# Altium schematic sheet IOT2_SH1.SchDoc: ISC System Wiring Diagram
size B; DrawnBy: Filiberto Clara; Engineer: Filiberto Clara; Organization: LIGO Laboratory; Address1: California Institute of Technology; Address2: Massachusetts Institute of Technology; SheetNumber: 24; SheetTotal: 37
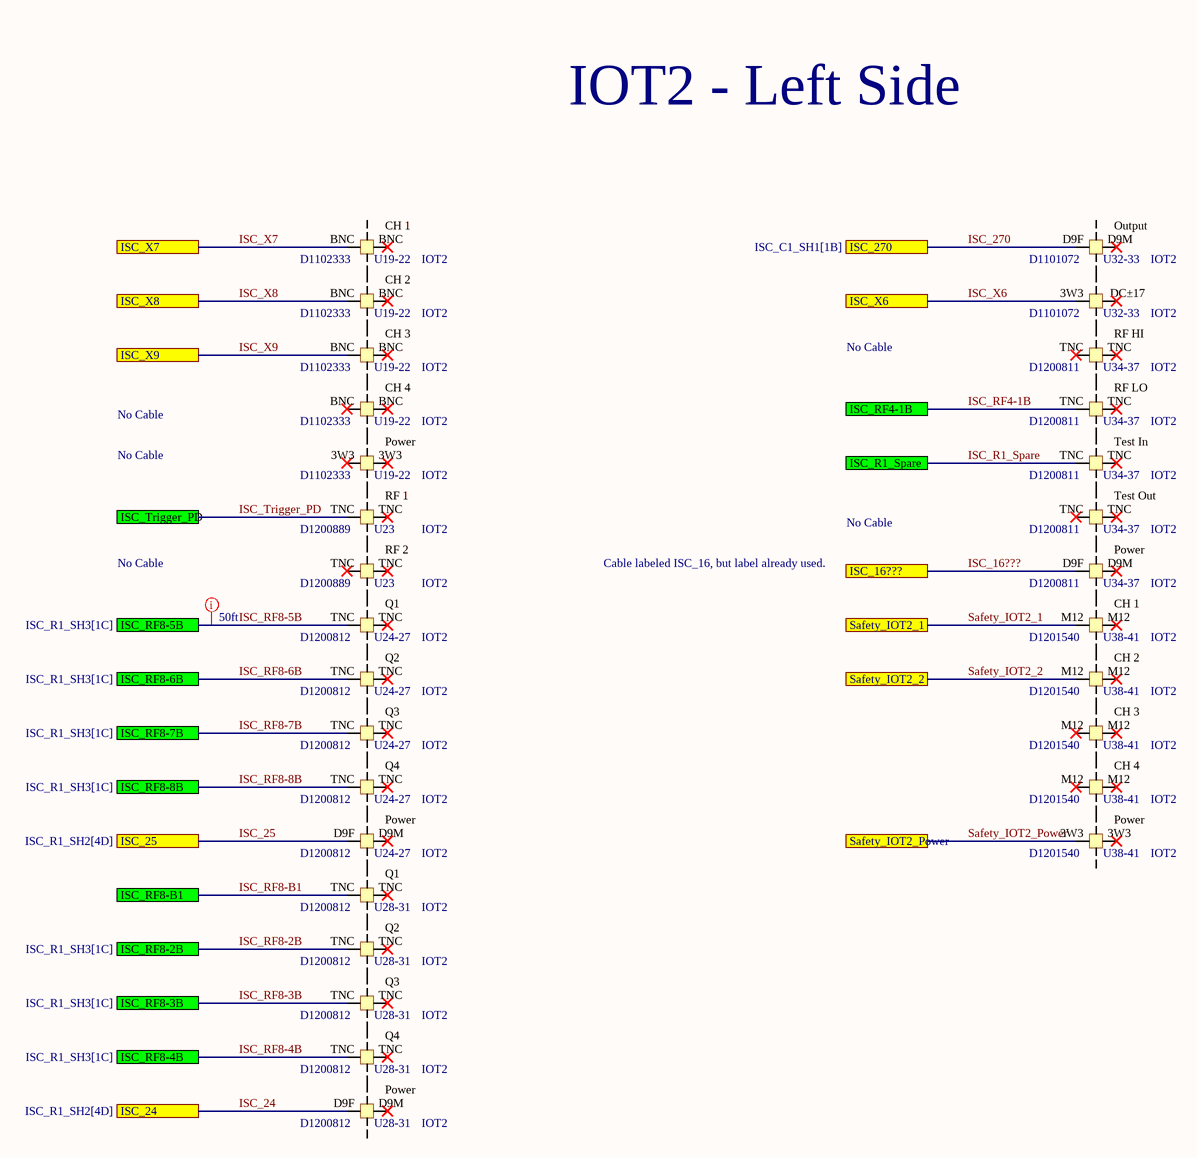
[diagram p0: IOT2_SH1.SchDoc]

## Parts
C_IOT2_1  DCC: D1102333  Rack: IOT2  Slot: U19-22  (hidden comment: Patch Panel Analog Video)  (parts A,B,C,D,E of 5)
C_IOT2_2  DCC: D1200889  Rack: IOT2  Slot: U23  (hidden comment: Patch Panel Broadband PD)  (parts A,B of 2)
C_IOT2_3  DCC: D1200812  Rack: IOT2  Slot: U24-27  (hidden comment: Patch Panel Single Frequency WFS RFPD)  (parts A,B,C,D,E of 5)
C_IOT2_4  DCC: D1200812  Rack: IOT2  Slot: U28-31  (hidden comment: Patch Panel Single Frequency WFS RFPD)  (parts A,B,C,D,E of 5)
C_IOT2_5  DCC: D1101072  Rack: IOT2  Slot: U32-33  (hidden comment: Patch Panel DCPD Interface)  (parts A,B of 2)
C_IOT2_6  DCC: D1200811  Rack: IOT2  Slot: U34-37  (hidden comment: Patch Panel Dual Frequency LSC RFPD)  (parts A,B,C,D,E of 5)
C_IOT2_7  DCC: D1201540  Rack: IOT2  Slot: U38-41  (hidden comment: Patch Panel Interlocks/Lighting)  (parts A,B,C,D,E of 5)

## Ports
ISC_16???, ISC_24 (see ISC_R1_SH2[4D]), ISC_25 (see ISC_R1_SH2[4D]), ISC_270 (see ISC_C1_SH1[1B]), ISC_R1_Spare, ISC_RF4-1B, ISC_RF8-2B (see ISC_R1_SH3[1C]), ISC_RF8-3B (see ISC_R1_SH3[1C]), ISC_RF8-4B (see ISC_R1_SH3[1C]), ISC_RF8-5B (see ISC_R1_SH3[1C]), ISC_RF8-6B (see ISC_R1_SH3[1C]), ISC_RF8-7B (see ISC_R1_SH3[1C]), ISC_RF8-8B (see ISC_R1_SH3[1C]), ISC_RF8-B1, ISC_Trigger_PD, ISC_X6, ISC_X7, ISC_X8, ISC_X9, Safety_IOT2_1, Safety_IOT2_2, Safety_IOT2_Power

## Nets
ISC_16???: C_IOT2_6.D9F(Power) ; port ISC_16???
ISC_24: C_IOT2_4.D9F(Power) ; port ISC_24
ISC_25: C_IOT2_3.D9F(Power) ; port ISC_25
ISC_270: C_IOT2_5.D9F(Output) ; port ISC_270
ISC_R1_Spare: C_IOT2_6.TNC(TestIn) ; port ISC_R1_Spare
ISC_RF4-1B: C_IOT2_6.TNC(RFHI) ; port ISC_RF4-1B
ISC_RF8-2B: C_IOT2_4.TNC(RFLO) ; port ISC_RF8-2B
ISC_RF8-3B: C_IOT2_4.TNC(TestIn) ; port ISC_RF8-3B
ISC_RF8-4B: C_IOT2_4.TNC(TestOut) ; port ISC_RF8-4B
ISC_RF8-5B: C_IOT2_3.TNC(RFHI) ; port ISC_RF8-5B
ISC_RF8-6B: C_IOT2_3.TNC(RFLO) ; port ISC_RF8-6B
ISC_RF8-7B: C_IOT2_3.TNC(TestIn) ; port ISC_RF8-7B
ISC_RF8-8B: C_IOT2_3.TNC(TestOut) ; port ISC_RF8-8B
ISC_RF8-B1: C_IOT2_4.TNC(RFHI) ; port ISC_RF8-B1
ISC_Trigger_PD: C_IOT2_2.TNC(RF1) ; port ISC_Trigger_PD
ISC_X6: C_IOT2_5.3W3(DC±17) ; port ISC_X6
ISC_X7: C_IOT2_1.BNC(CH_1) ; port ISC_X7
ISC_X8: C_IOT2_1.BNC(CH_2) ; port ISC_X8
ISC_X9: C_IOT2_1.BNC(CH_3) ; port ISC_X9
Safety_IOT2_1: C_IOT2_7.M12(CH_1) ; port Safety_IOT2_1
Safety_IOT2_2: C_IOT2_7.M12(CH_2) ; port Safety_IOT2_2
Safety_IOT2_Power: C_IOT2_7.3W3(Power) ; port Safety_IOT2_Power

Not connected (* = marked no-connect by the designer): C_IOT2_1 3W3(Power)*; C_IOT2_3 D9M(Power)*; C_IOT2_4 D9M(Power)*; C_IOT2_5 D9M(Output)*; C_IOT2_6 D9M(Power)*

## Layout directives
Length: 50ft: ISC_RF8-5B

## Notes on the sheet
- IOT2 - Left Side
- No Cable
- Cable labeled ISC_16, but label already used.

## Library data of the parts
C_IOT2_1 = Patch Panel Analog Video: Patch Panel (D1102333); Serial: Sxxxxxxx; System: ISC
C_IOT2_2 = Patch Panel Broadband PD: Patch Panel (D1200889); Serial: Sxxxxxxx; System: ISC
C_IOT2_3 C_IOT2_4 = Patch Panel Single Frequency WFS RFPD: Patch Panel (D1200812); Serial: Sxxxxxxx; System: ISC
C_IOT2_5 = Patch Panel DCPD Interface: Patch Panel (D1101072); Serial: Sxxxxxxx; System: ISC
C_IOT2_6 = Patch Panel Dual Frequency LSC RFPD: Patch Panel (D1200811); Serial: Sxxxxxxx; System: ISC
C_IOT2_7 = Patch Panel Interlocks/Lighting: Patch Panel Interlocks/Lighting (D1201540); Serial: Sxxxxxxx; System: ISC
